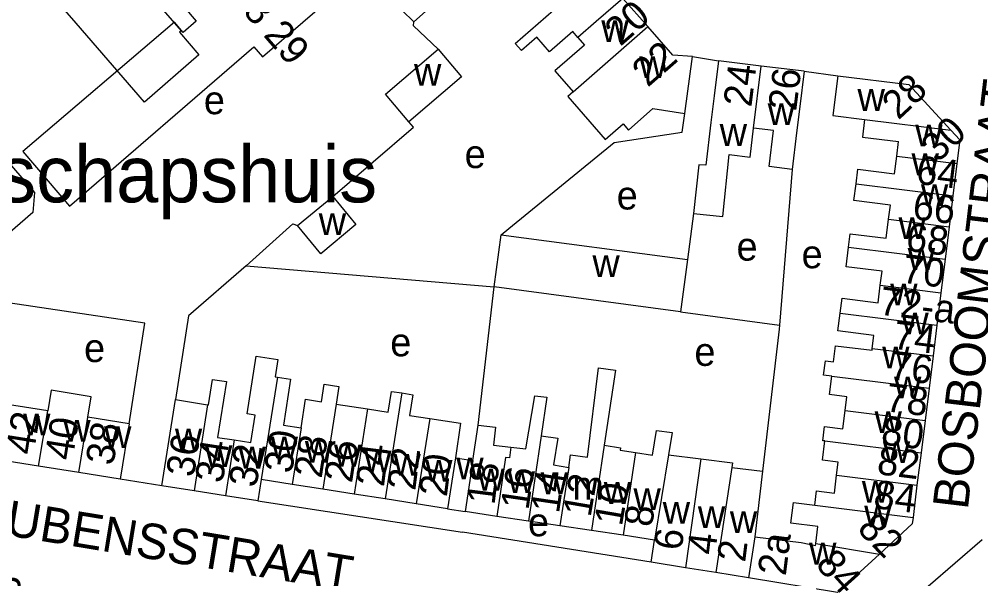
# Model space of a CAD drawing. Extents: x 161775 to 163181, y 382878 to 383925.
# Drawn here: x 162592 to 162727.8, y 383329.4 to 383408.5 of the extents above; entities that cross this region are included whole.
import ezdxf

# ---------------------------------------------------------------- set-up
doc = ezdxf.new("R2010")
doc.units = 0
for name, color, linetype in [('BLT_Basislijn', 7, 'Continuous'), ('BLT_Bebouwing', 7, 'Continuous'), ('BLT_Bebouwing_beschrifting', 7, 'Continuous'), ('BLT_Centroide', 7, 'Continuous'), ('BLT_Huisnummer', 7, 'Continuous'), ('BLT_Huisnummer_ tussenligend', 7, 'Continuous'), ('BLT_Huisnummer_reeks', 7, 'Continuous'), ('BLT_Huisnummer_zonder_bebouwing', 7, 'Continuous'), ('BLT_Onderdoorgang_en_onderverdeling', 7, 'Continuous'), ('BLT_Onderverdeling_panden', 7, 'Continuous'), ('BLT_Plantopo', 7, 'Continuous'), ('BLT_Straatnaam', 7, 'Continuous')]:
    doc.layers.add(name, color=color, linetype=linetype)

msp = doc.modelspace()

# ---------------------------------------------------------------- linework, layer by layer
at = {"layer": 'BLT_Basislijn'}
for p, q in [((162647.66, 383407.55), (162647.72, 383408.1)), ((162651.15, 383404.22), (162647.66, 383407.55)), ((162687.08, 383403.2), (162690.77, 383402.61)), ((162702.85, 383401.12), (162707.61, 383400.49)), ((162701.14, 383387.26), (162699.37, 383365.24)), ((162624.02, 383373.62), (162659.05, 383370.66)), ((162656.81, 383351.14), (162659.05, 383370.66)), ((162685.39, 383367.15), (162699.37, 383365.24)), ((162699.33, 383364.69), (162696.95, 383344.61)), ((162699.37, 383365.24), (162699.33, 383364.69)), ((162612.11, 383342.57), (162606.23, 383343.5)), ((162681.23, 383331.78), (162654.6, 383336.02))]:
    msp.add_line(p, q, dxfattribs=at)
for points in [[(162660.03, 383378.02), (162661.12, 383378.93), (162676, 383391.04), (162685.64, 383392.51), (162685.98, 383395.16)], [(162636.26, 383383.43), (162647.66, 383393.21), (162647, 383393.99)], [(162687.23, 383381.03), (162686.38, 383374.52)], [(162624.02, 383373.62), (162630.63, 383379.57), (162631.27, 383379.32)], [(162624.02, 383373.62), (162615.86, 383366.58), (162614.03, 383354.73)], [(162607.51, 383351.32), (162609.73, 383365.53), (162582.46, 383369.6)], [(162625.7, 383340.43), (162654.6, 383336.02)], [(162728.02, 383334.92), (162716.54, 383325.02), (162725.36, 383320.12), (162728.11, 383321.94)]]:
    msp.add_lwpolyline(points, dxfattribs=at)
at = {"layer": 'BLT_Bebouwing'}
for p, q in [((162647.72, 383408.1), (162644.41, 383411.33)), ((162680.77, 383407.44), (162677.25, 383411.46)), ((162643.69, 383397.87), (162651.15, 383404.22)), ((162617.36, 383403.43), (162609.66, 383396.77)), ((162685.98, 383395.16), (162687.08, 383403.2)), ((162696.79, 383401.86), (162690.77, 383402.61)), ((162702.85, 383401.12), (162696.79, 383401.86)), ((162707.61, 383400.49), (162706.91, 383394.88)), ((162647, 383393.99), (162643.69, 383397.87)), ((162706.91, 383394.88), (162711.39, 383394.32)), ((162724.43, 383388.08), (162723.86, 383383.51)), ((162594.11, 383383.99), (162593.91, 383381.16)), ((162723.86, 383383.51), (162723.32, 383379.15)), ((162631.27, 383379.32), (162636.26, 383383.43)), ((162593.91, 383381.16), (162590.31, 383378.05)), ((162723.32, 383379.15), (162722.76, 383374.59)), ((162659.05, 383370.66), (162660.03, 383378.02)), ((162660.03, 383378.02), (162686.38, 383374.52)), ((162686.38, 383374.52), (162685.39, 383367.15)), ((162722.76, 383374.59), (162722.16, 383369.83)), ((162685.39, 383367.15), (162659.05, 383370.66)), ((162722.16, 383369.83), (162721.6, 383365.27)), ((162721.6, 383365.27), (162721.06, 383360.9)), ((162721.06, 383360.9), (162720.49, 383356.34)), ((162720.49, 383356.34), (162719.93, 383351.78)), ((162595.99, 383353.15), (162590.32, 383354.05)), ((162612.11, 383342.57), (162614.03, 383354.73)), ((162614.03, 383354.73), (162618.58, 383354.01)), ((162636.75, 383354.1), (162641.19, 383353.42)), ((162719.93, 383351.78), (162719.36, 383347.22)), ((162683.69, 383346.94), (162688.26, 383346.38)), ((162719.36, 383347.22), (162718.79, 383342.65)), ((162594.71, 383345.33), (162589.04, 383346.23)), ((162653.61, 383346.51), (162656.06, 383346.12)), ((162606.23, 383343.5), (162600.38, 383344.43)), ((162692.63, 383345.14), (162696.95, 383344.61)), ((162696.95, 383344.61), (162695.87, 383335.35)), ((162626.17, 383343.45), (162625.7, 383340.43)), ((162630.55, 383342.76), (162626.17, 383343.45)), ((162634.85, 383342.09), (162630.55, 383342.76)), ((162616.66, 383341.85), (162612.11, 383342.57)), ((162621.1, 383341.15), (162616.66, 383341.85)), ((162639.3, 383341.39), (162634.85, 383342.09)), ((162643.68, 383340.7), (162639.3, 383341.39)), ((162718.79, 383342.65), (162718.23, 383338.09)), ((162625.7, 383340.43), (162621.1, 383341.15)), ((162648.05, 383340.01), (162643.68, 383340.7)), ((162652.48, 383339.31), (162648.05, 383340.01)), ((162652.48, 383339.31), (162654.97, 383338.91)), ((162659.43, 383338.24), (162654.97, 383338.91)), ((162663.89, 383337.57), (162659.43, 383338.24)), ((162668.35, 383336.9), (162663.89, 383337.57)), ((162672.81, 383336.23), (162668.35, 383336.9)), ((162677.27, 383335.57), (162672.81, 383336.23)), ((162681.73, 383334.89), (162677.27, 383335.57)), ((162681.23, 383331.78), (162681.73, 383334.89)), ((162686.08, 383330.99), (162681.23, 383331.78)), ((162690.37, 383330.29), (162686.08, 383330.99)), ((162694.99, 383329.54), (162690.37, 383330.29))]:
    msp.add_line(p, q, dxfattribs=at)
for points in [[(162609.66, 383396.77), (162600, 383407.9), (162590.12, 383419.29), (162589.48, 383418.74), (162587.25, 383421.31), (162579.44, 383414.56), (162563.18, 383400.54)], [(162604.73, 383418.5), (162614.84, 383406.83), (162614.6, 383406.62), (162617.36, 383403.43)], [(162657.49, 383416.73), (162655.58, 383415.1), (162647.72, 383408.1)], [(162670.88, 383405.89), (162670.16, 383406.72), (162666.89, 383403.86), (162665.09, 383405.92), (162662.94, 383404.04), (162662.05, 383405.06), (162667.43, 383409.77)], [(162687.08, 383403.2), (162684.32, 383403.38), (162680.77, 383407.44)], [(162670.88, 383405.89), (162671.82, 383404.82), (162667.63, 383401.16), (162670.21, 383398.21)], [(162651.15, 383404.22), (162654.46, 383400.34), (162647, 383393.99)], [(162690.77, 383402.61), (162690.15, 383397.65), (162689.69, 383393.87), (162688.94, 383387.83)], [(162563.18, 383400.54), (162563.84, 383399.78), (162565.27, 383399.68), (162571.02, 383393.04), (162570.82, 383390.22), (162572.15, 383390.12), (162575.31, 383392.86), (162575.48, 383395.12), (162579.17, 383398.32), (162581.88, 383398.12), (162594.11, 383383.99)], [(162702.85, 383401.12), (162702.23, 383396.15), (162701.77, 383392.44), (162701.14, 383387.26)], [(162707.61, 383400.49), (162717.64, 383399.25), (162723.57, 383392.81)], [(162670.21, 383398.21), (162669.45, 383397.54), (162674.75, 383391.49), (162677.27, 383393.69), (162678.04, 383392.82), (162681.49, 383395.84), (162685.98, 383395.16)], [(162687.23, 383381.03), (162691.36, 383380.59), (162692.28, 383389.34), (162695.21, 383388.98), (162695.7, 383393.09)], [(162701.14, 383387.26), (162697.9, 383387.66), (162698.53, 383392.74), (162695.7, 383393.09)], [(162711.39, 383394.32), (162711.08, 383391.81), (162716.18, 383391.18)], [(162723.56, 383392.81), (162724.84, 383391.42), (162724.43, 383388.08)], [(162715.93, 383389.13), (162716.18, 383391.18)], [(162710.18, 383385.21), (162710.43, 383387.28), (162715.62, 383386.64), (162715.93, 383389.13)], [(162688.94, 383387.83), (162687.97, 383387.91), (162687.23, 383381.03)], [(162714.79, 383380.21), (162715.03, 383382.21), (162709.88, 383382.85), (162710.18, 383385.21)], [(162636.26, 383383.43), (162639.54, 383379.45), (162634.56, 383375.34), (162631.27, 383379.32)], [(162709.13, 383376.28), (162709.36, 383378.17), (162714.46, 383377.54), (162714.79, 383380.21)], [(162713.6, 383370.89), (162713.85, 383372.88), (162708.79, 383373.5), (162709.13, 383376.28)], [(162707.94, 383366.96), (162708.2, 383369.05), (162713.3, 383368.41), (162713.6, 383370.89)], [(162712.48, 383361.97), (162712.71, 383363.81), (162707.62, 383364.44), (162707.94, 383366.96)], [(162706.76, 383358.04), (162705.6, 383358.19), (162705.85, 383360.2), (162707.01, 383360.06), (162707.29, 383362.34), (162712.45, 383361.7), (162712.48, 383361.97)], [(162622.32, 383349.03), (162624.69, 383348.66), (162625.3, 383352.54), (162624.17, 383352.72), (162625.43, 383360.86), (162628.51, 383360.38), (162628.14, 383357.97), (162628.46, 383357.91)], [(162669.59, 383345.16), (162669.86, 383346.92), (162672.24, 383346.62), (162673.81, 383359.21), (162676.22, 383358.91), (162674.62, 383348.28)], [(162628.46, 383357.91), (162630.31, 383357.63), (162629.31, 383351.13), (162631.81, 383350.75)], [(162708.63, 383353.18), (162708.88, 383355.15), (162706.44, 383355.45), (162706.76, 383358.04)], [(162618.58, 383354.01), (162618.73, 383353.99), (162619.29, 383357.59), (162621.23, 383357.28), (162620, 383349.4), (162622.32, 383349.03)], [(162631.81, 383350.75), (162632.43, 383354.78), (162634.65, 383354.44), (162635.03, 383356.9), (162637.14, 383356.57), (162636.75, 383354.1)], [(162601.66, 383352.25), (162602.14, 383355.14), (162596.47, 383356.07), (162595.99, 383353.15)], [(162641.19, 383353.42), (162644.09, 383352.97), (162644.56, 383355.9), (162646.04, 383355.67)], [(162646.04, 383355.67), (162647.55, 383355.43), (162647.08, 383352.5), (162649.96, 383352.06)], [(162661.41, 383348.02), (162663.53, 383347.76), (162664.82, 383355.29), (162666.52, 383355.08), (162665.7, 383349.62)], [(162607.51, 383351.32), (162601.66, 383352.25)], [(162705.75, 383348.9), (162705.48, 383348.93), (162705.73, 383350.94), (162708.31, 383350.62), (162708.63, 383353.18)], [(162607.51, 383351.32), (162606.23, 383343.5)], [(162649.96, 383352.06), (162654.31, 383351.39), (162653.61, 383346.51)], [(162656.06, 383346.12), (162656.81, 383351.14)], [(162656.81, 383351.14), (162659.27, 383350.84), (162658.96, 383348.32), (162661.41, 383348.02)], [(162665.7, 383349.62), (162668.07, 383349.27), (162667.45, 383345.53), (162669.59, 383345.16)], [(162679.03, 383347.26), (162681.43, 383346.9), (162681.99, 383350.35), (162684.2, 383350.08), (162683.69, 383346.94)], [(162674.62, 383348.28), (162676.9, 383347.94), (162676.84, 383347.59), (162679.03, 383347.26)], [(162707.43, 383344.06), (162707.66, 383345.91), (162705.42, 383346.19), (162705.75, 383348.9)], [(162688.26, 383346.38), (162692.74, 383345.82), (162692.63, 383345.14)], [(162600.38, 383344.43), (162594.71, 383345.33)], [(162704.35, 383339.81), (162704.6, 383341.85), (162707.12, 383341.54), (162707.43, 383344.06)], [(162704.5, 383334.39), (162704.8, 383336.83), (162700.99, 383337.3), (162701.35, 383340.18), (162704.35, 383339.81)], [(162718.23, 383338.09), (162718.12, 383337.17), (162713.49, 383332.92)], [(162695.87, 383335.35), (162702.44, 383334.53), (162704.47, 383334.14), (162704.5, 383334.39)], [(162713.49, 383332.92), (162707.58, 383327.5), (162694.99, 383329.54)]]:
    msp.add_lwpolyline(points, dxfattribs=at)
at = {"layer": 'BLT_Onderdoorgang_en_onderverdeling'}
for p, q in [((162653.61, 383346.51), (162652.48, 383339.31)), ((162656.06, 383346.12), (162654.97, 383338.91))]:
    msp.add_line(p, q, dxfattribs=at)
at = {"layer": 'BLT_Onderverdeling_panden'}
for p, q in [((162670.21, 383398.21), (162680.77, 383407.44)), ((162695.7, 383393.09), (162696.79, 383401.86)), ((162711.39, 383394.32), (162723.57, 383392.81)), ((162715.93, 383389.13), (162724.43, 383388.08)), ((162710.18, 383385.21), (162723.86, 383383.51)), ((162714.79, 383380.21), (162723.32, 383379.15)), ((162709.13, 383376.28), (162722.76, 383374.59)), ((162713.6, 383370.89), (162722.16, 383369.83)), ((162707.94, 383366.96), (162721.6, 383365.27)), ((162628.46, 383357.91), (162626.17, 383343.45)), ((162706.76, 383358.04), (162720.49, 383356.34)), ((162646.04, 383355.67), (162643.68, 383340.7)), ((162618.58, 383354.01), (162616.66, 383341.85)), ((162636.75, 383354.1), (162634.85, 383342.09)), ((162641.19, 383353.42), (162639.3, 383341.39)), ((162708.63, 383353.18), (162719.93, 383351.78)), ((162649.96, 383352.06), (162648.05, 383340.01)), ((162631.81, 383350.75), (162630.55, 383342.76)), ((162665.7, 383349.62), (162663.89, 383337.57)), ((162674.62, 383348.28), (162672.81, 383336.23)), ((162679.03, 383347.26), (162677.27, 383335.57)), ((162683.69, 383346.94), (162681.73, 383334.89)), ((162688.26, 383346.38), (162686.08, 383330.99)), ((162669.59, 383345.16), (162668.35, 383336.9)), ((162692.63, 383345.14), (162690.37, 383330.29)), ((162707.43, 383344.06), (162718.79, 383342.65)), ((162695.87, 383335.35), (162694.99, 383329.54)), ((162704.5, 383334.39), (162713.49, 383332.92))]:
    msp.add_line(p, q, dxfattribs=at)
for points in [[(162677.25, 383411.46), (162673.45, 383408.13), (162670.88, 383405.89)], [(162712.48, 383361.97), (162721.06, 383360.9)], [(162594.71, 383345.33), (162595.99, 383353.15)], [(162600.38, 383344.43), (162601.66, 383352.25)], [(162622.32, 383349.03), (162621.1, 383341.15)], [(162705.75, 383348.9), (162719.36, 383347.22)], [(162661.41, 383348.02), (162661.22, 383346.51), (162660.68, 383346.58), (162659.43, 383338.24)], [(162704.35, 383339.81), (162718.23, 383338.09)]]:
    msp.add_lwpolyline(points, dxfattribs=at)
at = {"layer": 'BLT_Plantopo'}
msp.add_lwpolyline([(162599.14, 383454.21), (162594.44, 383450.2), (162598.08, 383445.94), (162590.33, 383439.32), (162593.54, 383435.55), (162591.04, 383433.42), (162596.84, 383426.62), (162599.41, 383428.81), (162616.98, 383408.21), (162615.12, 383406.61), (162613.89, 383408.06), (162592.49, 383389.8), (162599.09, 383382.08), (162625.13, 383404.55), (162626.34, 383403.15), (162637.73, 383412.98), (162632.5, 383419.05), (162626.02, 383413.46), (162605.37, 383437.4), (162611.23, 383442.45)], close=True, dxfattribs=at)

# ---------------------------------------------------------------- texts
at = {"layer": 'BLT_Bebouwing_beschrifting'}
msp.add_text('Gemeenschapshuis', height=8, dxfattribs=at).set_placement((162547.98, 383382.6))
at = {"layer": 'BLT_Centroide'}
for s, p in [('w', (162674.2, 383405.23)), ('w', (162679.56, 383400.16)), ('w', (162647.74, 383399.09)), ('w', (162710.39, 383395.52)), ('e', (162618.05, 383395.05)), ('w', (162697.7, 383393.51)), ('w', (162690.92, 383390.58)), ('w', (162718.54, 383390.5)), ('e', (162654.89, 383387.44)), ('w', (162718.02, 383386.44)), ('w', (162719.35, 383382.09)), ('e', (162676.37, 383381.59)), ('w', (162634.28, 383377.98)), ('w', (162716.19, 383377.41)), ('e', (162693.3, 383374.37)), ('e', (162702.49, 383373.29)), ('w', (162717.48, 383373.06)), ('w', (162672.94, 383372.06)), ('w', (162715.01, 383368.06)), ('w', (162716.58, 383363.94)), ('e', (162601.13, 383360.04)), ('e', (162644.38, 383360.85)), ('e', (162687.35, 383359.5)), ('w', (162713.87, 383359.16)), ('w', (162715.55, 383354.91)), ('w', (162592.52, 383349.7)), ('w', (162712.8, 383350.03)), ('w', (162598.19, 383348.8)), ('w', (162603.95, 383347.88)), ('w', (162613.96, 383347.58)), ('w', (162627.49, 383346.45)), ('w', (162618.21, 383345.2)), ('w', (162632.32, 383345.83)), ('w', (162636.45, 383345.28)), ('w', (162713.97, 383345.78)), ('w', (162622.94, 383345)), ('w', (162640.7, 383344.46)), ('w', (162644.83, 383344)), ('w', (162649.31, 383343.14)), ('w', (162653.71, 383343.47)), ('w', (162656.68, 383341.89)), ('w', (162660.97, 383341.54)), ('w', (162665.63, 383341.37)), ('m', (162670.11, 383340.59)), ('w', (162674.55, 383340.01)), ('w', (162711, 383340.17)), ('w', (162678.74, 383339.12)), ('w', (162682.87, 383337.19)), ('w', (162687.84, 383336.58)), ('w', (162692.36, 383335.89)), ('w', (162711.33, 383336.69)), ('e', (162663.84, 383335.43)), ('w', (162703.55, 383331.44))]:
    msp.add_text(s, height=4, dxfattribs=at).set_placement(p)
at = {"layer": 'BLT_Huisnummer'}
for s, rotation, p in [('20', 41.1892, (162676.88, 383404.54)), ('22', 41.1908, (162680.75, 383398.77)), ('24', 82.9643, (162695.39, 383395.97)), ('26', 82.9643, (162701.72, 383395.41)), ('28', 42.9621, (162716.16, 383394.14)), ('30', 42.9621, (162721.69, 383388.09)), ('66', 352.9373, (162718.04, 383380.25)), ('70', 352.9469, (162716.55, 383371.27)), ('74', 352.9364, (162715.27, 383361.94)), ('78', 352.9438, (162714.21, 383353.11)), ('42', 81.004, (162594, 383346.81)), ('38', 80.9991, (162605.27, 383345.34)), ('36', 81.256, (162616.63, 383343.66)), ('30', 81.2439, (162630.49, 383344.2)), ('34', 81.2439, (162620.71, 383342.83)), ('26', 81.2411, (162638.97, 383342.86)), ('22', 82.9361, (162647.91, 383341.79)), ('20', 82.9433, (162652.37, 383340.91)), ('82', 352.9424, (162713.02, 383344.22)), ('18', 82.9433, (162659.1, 383339.77)), ('14', 81.5898, (162668.21, 383338.56)), ('10', 80.2496, (162677.1, 383336.75)), ('82', 314.0299, (162710.18, 383336.36)), ('6', 82.9433, (162685.55, 383333.32)), ('2', 82.9433, (162694.51, 383331.67))]:
    msp.add_text(s, height=4, rotation=rotation, dxfattribs=at).set_placement(p)
at = {"layer": 'BLT_Huisnummer_ tussenligend'}
for s, rotation, p in [('64', 352.9373, (162718.52, 383385.26)), ('68', 352.9469, (162717.08, 383375.78)), ('76', 352.9438, (162714.84, 383357.65)), ('80', 352.9424, (162713.6, 383348.42)), ('40', 80.9991, (162599.49, 383346.02)), ('28', 81.2411, (162634.68, 383343.52)), ('32', 81.2439, (162625.48, 383342.22)), ('24', 82.9361, (162643.48, 383342.33)), ('16', 81.5898, (162663.9, 383339.04)), ('12', 80.2496, (162672.68, 383338.03)), ('84', 352.9373, (162712.52, 383339.44)), ('8', 82.9433, (162681.38, 383336.64)), ('4', 82.9433, (162690.27, 383332.7)), ('33', 81.1481, (162591.41, 383323.77))]:
    msp.add_text(s, height=4, rotation=rotation, dxfattribs=at).set_placement(p)
at = {"layer": 'BLT_Huisnummer_reeks'}
for s, rotation, p in [('72-a', 352.9364, (162713.33, 383366.76)), ('2a', 82.9404, (162700.25, 383329.75)), ('84', 311.8931, (162704.31, 383331.37))]:
    msp.add_text(s, height=4, rotation=rotation, dxfattribs=at).set_placement(p)
at = {"layer": 'BLT_Huisnummer_zonder_bebouwing'}
msp.add_text('146 01 t/m 148 29', height=4, rotation=310.8886, dxfattribs=at).set_placement((162602.02, 383434.29))
at = {"layer": 'BLT_Straatnaam'}
for s, rotation, p in [('BOSBOOMSTRAAT', 83.2276, (162725.96, 383339.08)), ('RUBENSSTRAAT', 350.6675, (162585.12, 383336.4))]:
    msp.add_text(s, height=5, rotation=rotation, dxfattribs=at).set_placement(p)

doc.saveas('drawing.dxf')
